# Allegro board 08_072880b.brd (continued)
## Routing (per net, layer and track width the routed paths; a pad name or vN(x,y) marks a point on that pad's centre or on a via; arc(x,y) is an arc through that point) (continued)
P5V0: length 3.1
  TOP w0.508: 41.02,55.31 J3.2 40.26,54.55 ; 44.32,54.55 J3.6 43.56,55.31
VCC: length 14.4
  TOP w0.127: 40.65,42.51 40.45,42.3 40.45,41.52 40.27,41.34 39.87,41.34 39.65,41.12 39.65,38.94 U1.E7
  TOP w0.203: 40.65,42.51 41.11,42.51 VCC.1 P3.2
3P3VAUX: length 3.2
  TOP w0.203: v1(65.31,17.72) C9.1 U4.8
  BOTTOM w0.508: 71.75,15.18 v1(72.39,15.81)
AINA+: length 23.6
  TOP w0.203: LKA.1 34.48,26.44 36.19,24.73 36.19,23.35 35.69,22.85 33.26,22.85 27.65,17.23 27.65,14.73 27.44,14.53 JP3.2 R70.2
AINA-: length 23.2
  TOP w0.203: JP2.1 JP4.2 28.41,14.53 28.21,14.73 28.21,17 33.49,22.29 35.92,22.29 36.75,23.11 36.75,24.9 36.76,24.91 37.36,25.51 38.29,26.44 LKA.7
AINB+: length 23.6
  TOP w0.203: R43.2 JP7.2 13.64,27.44 13.84,27.24 16.11,27.24 21.4,32.53 21.4,34.96 22.22,35.78 24.01,35.78 24.02,35.79 24.62,36.39 25.55,37.33 LKB.1
AINB-: length 23.3
  TOP w0.203: LKB.7 25.55,33.52 23.84,35.22 22.46,35.22 21.96,34.73 21.96,32.3 16.34,26.68 13.84,26.68 13.64,26.48 JP8.2 JP6.1
AINC+: length 23.2
  TOP w0.203: LKC.2 25.55,39.76 24.62,40.7 24.02,41.3 24.01,41.31 22.22,41.31 21.4,42.13 21.4,44.56 16.11,49.85 13.84,49.85 13.64,49.64 JP11.2 R59.2
AINC-: length 23.7
  TOP w0.203: JP10.3 JP12.2 13.64,50.61 13.84,50.41 16.34,50.41 21.96,44.79 21.96,42.36 22.46,41.87 23.84,41.87 25.55,43.57 LKC.8
AIND+: length 23.2
  TOP w0.203: LKD.2 34.48,50.65 36.19,52.36 36.19,53.74 35.69,54.24 33.26,54.24 27.65,59.86 27.65,62.36 27.44,62.56 JP15.2 JP13.1
AIND-: length 23.6
  TOP w0.203: JP14.3 JP16.2 28.41,62.56 28.21,62.36 28.21,60.09 33.49,54.8 35.92,54.8 36.75,53.98 36.75,52.19 36.76,52.18 37.36,51.58 38.29,50.65 LKD.8
BIA+: length 5.8
  TOP w0.203: JP1.1 v1(23.52,12.76)
  BOTTOM w0.203: R9.1 20.03,15 22.26,12.76 v1(23.52,12.76)
BIA-: length 6.3
  TOP w0.203: JP2.3 v1(32.01,12.76)
  BOTTOM w0.203: R11.1 35.37,16.13 v1(32.01,12.76)
BIB+: length 5.8
  TOP w0.203: JP5.1 v1(11.87,31.38)
  BOTTOM w0.203: R38.1 14.11,34.87 11.87,32.64 v1(11.87,31.38)
BIB-: length 6.3
  TOP w0.203: JP6.3 v1(11.87,22.9)
  BOTTOM w0.203: v1(11.87,22.9) 15.24,19.53 R39.1
BIC+: length 4.7
  TOP w0.203: v1(11.87,46.09) 12,46.09 12,46.09 JP9.3
  BOTTOM w0.203: v1(11.87,46.09) 11.87,45.39 13.67,43.6 R50.1
BIC-: length 4.1
  TOP w0.203: JP10.1 v1(11.87,54.57)
  BOTTOM w0.203: v1(11.87,54.57) 11.87,56.54 12.27,56.94 R55.1
BID+: length 4.7
  TOP w0.203: JP13.3 v1(23.9,64.33)
  BOTTOM w0.203: v1(23.9,64.33) 23.19,64.33 21.41,62.54 R66.1
BID-: length 4.1
  TOP w0.203: JP14.1 v1(32.39,64.33)
  BOTTOM w0.203: R67.1 34.75,63.93 34.35,64.33 v1(32.39,64.33)
BOA+: length 11.2
  TOP w0.203: JP3.1 v1(25.9,13.53)
  BOTTOM w0.203: v1(25.9,13.53) 23.59,13.53 21.09,16.02 C20.2 R36.2 C24.2 A1.1
BOA-: length 12
  TOP w0.203: JP4.1 v1(29.96,13.53)
  BOTTOM w0.203: A1.7 C25.2 R37.2 C21.2 34.43,16.19 31.76,13.53 v1(29.96,13.53)
BOB+: length 11.2
  TOP w0.203: JP7.1 v1(12.64,28.99)
  BOTTOM w0.203: v1(12.64,28.99) 12.64,31.31 15.14,33.81 C33.2 R48.2 C37.2 A2.1
BOB-: length 12
  TOP w0.203: JP8.1 v1(12.64,24.93)
  BOTTOM w0.203: v1(12.64,24.93) 12.64,23.14 15.3,20.47 C34.2 R49.2 C38.2 A2.7
BOC+: length 19.3
  TOP w0.203: JP11.1 v1(12.64,48.09)
  BOTTOM w0.203: A3.1 C47.2 R64.2 C43.2 19.54,43.03 18.44,41.92 13.86,41.92 11.29,44.49 11.29,46.75 v1(12.64,48.09)
BOC-: length 19.1
  TOP w0.203: JP12.1 v1(12.64,52.16)
  BOTTOM w0.203: A3.7 C48.2 R65.2 C44.2 18.27,57.63 17.29,58.61 12.46,58.61 11.32,57.47 11.32,53.42 12.18,52.55 12.24,52.55 v1(12.64,52.16)
BOD+: length 19.3
  TOP w0.203: JP15.1 v1(25.9,63.56)
  BOTTOM w0.203: v1(25.9,63.56) 24.57,64.88 22.26,64.88 19.74,62.36 19.74,57.76 20.84,56.66 C53.2 R79.2 C57.2 A4.1
BOD-: length 19.1
  TOP w0.203: JP16.1 v1(29.96,63.56)
  BOTTOM w0.203: v1(29.96,63.56) 30.35,63.96 30.35,64.02 31.22,64.88 35.27,64.88 36.44,63.72 36.44,58.92 35.45,57.93 C54.2 R80.2 C58.2 A4.7
CSN: length 6.1
  TOP w0.203: R16.1 42.95,34.81 42.55,35.21 v1(42.55,36.14) 41.97,36.14 41.97,36.14 U1.H9
  BOTTOM w0.203: v1(42.55,36.14) 42.55,35.33 43.07,34.81 R16.1
ENABLE: length 22.6
  BOTTOM w0.127: 40.55,37.34 35.8,37.34 35.65,37.49 35.65,38.15 v2(35.26,38.54)
  BOTTOM w0.203: 40.55,37.34 41.29,36.6 41.29,34.91 45.55,30.65 51.78,30.65 52.13,30.29 ENABLE.2
GA0: length 7.1
  TOP w0.203: v1(73.66,13.27) 72.9,14.03 69.44,14.03 68.83,13.42 U4.2
  BOTTOM w0.203: P1.C34 v1(73.66,13.27)
GA1: length 14.1
  TOP w0.203: U4.1 67.56,13.42 68.65,14.51 73.31,14.51 74.23,13.59 74.23,12.57 72.39,10.73 v1(71.12,10.73)
  BOTTOM w0.203: 71.75,11.37 v1(71.12,10.73)
IN_LDO: length 20.4
  TOP w0.203: v2(37.66,39.34) U1.C5 U1.C6
  BOTTOM w0.127: 40.45,42.02 40.45,40.58 39.62,39.75 38.06,39.75 v2(37.66,39.34)
  BOTTOM w0.203: 40.45,42.02 42.8,44.37 42.8,47.75 IN_LDO.1 45.4,51.44 J3.5
INA+: length 12.8
  TOP w0.203: A+.1 INA+.1 R70.1 R1.2
INA-: length 12.8
  TOP w0.203: A-.1 INA-.1 JP2.2 R2.2
INB+: length 12.8
  TOP w0.203: R3.2 R43.1 INB+.1 B+.1
INB-: length 12.8
  TOP w0.203: R4.2 JP6.2 INB-.1 B-.1
INC+: length 12.8
  TOP w0.203: C+.1 INC+.1 R59.1 R5.2
INC-: length 12.6
  TOP w0.203: R6.2 JP10.2 INC-.1 C-.1
IND+: length 12.8
  TOP w0.203: D+.1 IND+.1 JP13.2 R7.2
IND-: length 12.7
  TOP w0.203: R8.2 JP14.2 IND-.1 D-.1
OUT_LDO: length 12.4
  TOP w0.203: OUT_LDO.1 53.52,49.34 J2.1 51.31,49.34 50.04,48.07 P3.1 ; U1.D6 v2(39.26,39.34)
  L3_PWR w0.508: P3.1 47.5,48.07 ; P3.1 48.51,48.83 ; P3.1 49.53,48.07
OUTA+: length 13.5
  BOTTOM w0.127: v2(39.26,36.14) 39.04,36.14 38.64,36.54 38.2,36.54 38.06,36.41 38.06,35.69
  BOTTOM w0.203: C2.2 37.44,33.65 37.95,34.15 37.95,34.16 38.06,34.27 38.06,35.69 ; v2(39.26,36.14) 39.26,33.77 40.83,32.19 v1(40.83,27.72)
OUTA-: length 13.3
  BOTTOM w0.203: 39.13,32.62 39.56,32.19 v1(39.56,27.53) ; 39.13,32.62 38.7,32.19 36.65,32.19 36.45,32.4 C1.2 ; 39.13,32.62 38.46,33.3 v2(38.46,36.14)
OUTB+: length 14.9
  BOTTOM w0.127: 34.74,36.54 35.88,36.54 36.06,36.36 v2(36.06,36.14)
  BOTTOM w0.203: 34.74,36.54 34.71,36.58 33.29,36.58 32.76,37.11 C4.2
  BOTTOM w0.254: v1(27.6,30.98) 31.67,30.98 36.06,35.36 v2(36.06,36.14)
OUTB-: length 16.8
  BOTTOM w0.203: C3.2 32.13,38.1 31.78,37.75 31.78,36.1 33.91,33.97
  BOTTOM w0.254: v2(35.26,36.14) 35.26,35.32 32.13,32.19 v1(26.34,32.19)
OUTC+: length 15.9
  BOTTOM w0.127: 34.1,41.35 34.61,41.35 34.86,41.1 34.86,40.7 35.03,40.54 35.65,40.54 v2(36.06,40.94)
  BOTTOM w0.203: v2(36.06,40.94) 36.06,41.73 31.69,46.1 v1(27.6,46.1) ; 34.1,41.35 33.28,41.35 32.79,40.86 C6.2
OUTC-: length 16.4
  BOTTOM w0.203: v1(26.34,44.83) 32.19,44.83 33.88,43.15 ; 33.88,43.15 35.26,41.77 v2(35.26,40.94) ; 33.88,43.15 31.94,41.21 31.94,39.54 32.2,39.28 C5.2
OUTD+: length 13.6
  BOTTOM w0.127: 38.06,41.35 38.06,40.68 38.23,40.51 38.82,40.51 v2(39.26,40.94)
  BOTTOM w0.152: C8.2 37.38,43.44 38.06,42.76
  BOTTOM w0.203: 38.06,42.76 38.06,41.35 ; v2(39.26,40.94) 39.26,42.94 40.83,44.51 v1(40.83,49.4)
OUTD-: length 13.6
  BOTTOM w0.203: v2(38.46,40.94) 38.46,43.41 39.56,44.51 39.56,45.02 ; 39.56,45.02 v1(39.56,49.59) ; 39.56,45.02 36.85,45.02 36.45,44.63 C7.2
PMODE: length 21.4
  BOTTOM w0.127: v2(36.06,38.54) 36.45,38.15 40.66,38.15
  BOTTOM w0.203: MODE.2 52.13,31.43 51.78,31.08 45.76,31.08 41.68,35.15 41.68,37.13 40.66,38.15
R1A+: length 11.9
  TOP w0.203: U1.J6 38.23,35.12 38.23,34.23 38.46,34 38.46,33.67 39.56,32.56 LKA.10 39.56,30.16 39.18,29.78 36.13,29.78 35.75,29.4 LKA.3
R1A-: length 11.7
  TOP w0.203: U1.J7 39.26,34.14 40.83,32.56 LKA.12 40.83,29.86 40.25,29.27 37.53,29.27 37.02,28.77 LKA.5
R1B+: length 14.4
  TOP w0.254: U1.J2 34.79,34.87 32.7,34.87 32.45,34.62 32.45,32.54 32.16,32.25 LKB.10 29.62,32.25 28.89,32.97 28.89,35.8 28.64,36.06 LKB.3
R1B-: length 14.6
  TOP w0.254: U1.J3 31.69,30.98 LKB.12 28.92,30.98 28.38,31.51 28.38,34.53 28.13,34.79 LKB.5
R1C+: length 14.4
  TOP w0.203: LKC.4 28.59,41.03 28.79,41.24 28.79,44.02 29.62,44.84 LKC.9
  TOP w0.254: U1.A2 34.79,42.21 32.7,42.21 32.45,42.47 32.45,44.55 32.16,44.84 LKC.9
R1C-: length 14.4
  TOP w0.203: LKC.6 27.61,42.3 28.38,43.08 28.38,45.73 28.77,46.11 LKC.11 31.69,46.11 U1.A3
R1D+: length 11.7
  TOP w0.203: U1.A6 38.23,41.97 38.23,42.86 38.46,43.09 38.46,43.42 39.56,44.53 LKD.9 39.56,46.58 38.84,47.31 36.13,47.31 35.75,47.69 LKD.4
R1D-: length 11.8
  TOP w0.203: U1.A7 39.26,42.95 40.83,44.53 LKD.11 40.83,47.18 40.2,47.82 37.27,47.82 37.02,48.07 LKD.6
R2A+: length 5.5
  TOP w0.203: U1.J4 35.75,34.24 LKA.4 LKA.2
R2A-: length 5.5
  TOP w0.203: U1.J5 36.83,34.52 36.83,33.43 37.02,33.24 LKA.6 LKA.8
R2B+: length 6
  TOP w0.254: U1.F1 33.11,37.74 32.58,37.21 32.58,36.91 31.67,36 30.7,36 LKB.4 LKB.2
R2B-: length 6
  TOP w0.254: LKB.8 LKB.6 30.7,34.73 31.67,34.73 33.88,36.94 U1.G1
R2C+: length 6
  TOP w0.203: LKC.1 LKC.3
  TOP w0.254: U1.D1 33.11,39.34 32.58,39.88 32.58,40.18 31.67,41.08 30.7,41.08 LKC.3
R2C-: length 6
  TOP w0.203: U1.C1 33.83,40.14 31.67,42.3 LKC.5 LKC.7
R2D+: length 5.5
  TOP w0.203: U1.A4 35.75,42.85 LKD.3 LKD.1
R2D-: length 5.5
  TOP w0.203: U1.A5 36.83,42.57 36.83,43.66 37.02,43.85 LKD.5 LKD.7
REFSNS: length 4.8
  TOP w0.203: REFS.1 45.4,33.33 45.19,33.54 R81.2
SCL: length 5.9
  TOP w0.203: U4.6 70.1,18.5 70.71,19.11 73.03,19.11 v1(73.72,18.41)
  BOTTOM w0.203: P1.C30 v1(73.72,18.41)
SCLK: length 5.3
  TOP w0.203: R23.1 R15.1 43.43,39.34 v1(42.55,39.34) U1.D9
  BOTTOM w0.203: R15.1 43.43,39.34 v1(42.55,39.34)
SCLK_R: length 26.4
  TOP w0.203: R23.2 48.66,40.14 52.9,44.39 58.55,44.39 v1(62.36,48.2)
  BOTTOM w0.203: v1(62.36,48.2) 64.14,48.2 66.67,50.74
SDA: length 3.6
  TOP w0.203: U4.5 73.15,17.72 v1(73.72,17.14)
  BOTTOM w0.203: P1.C31 v1(73.72,17.14)
SDI: length 4.4
  TOP w0.203: R19.1 43.62,38.01 43.09,38.54 v1(42.55,38.54) U1.E9
  BOTTOM w0.203: R19.1 43.62,38.01 43.09,38.54 42.66,38.54 42.65,38.54 42.55,38.54 v1(42.55,38.54)
SDOA: length 4.9
  TOP w0.203: R13.1 43.62,35.88 v1(42.55,36.94) 41.97,36.94 41.97,36.94 U1.G9
  BOTTOM w0.203: v1(42.55,36.94) 43.62,35.88 R13.1
SDOB: length 4.6
  TOP w0.203: R14.1 43.65,36.94 42.85,37.74 v1(42.55,37.74) U1.F9
  BOTTOM w0.203: v1(42.55,37.74) 42.82,37.74 43.62,36.94 R14.1
SDOC: length 4.4
  TOP w0.203: R20.1 43.62,41.21 v1(42.55,40.14) 41.97,40.14 41.97,40.14 U1.C9
  BOTTOM w0.203: R29.2 v1(42.55,40.14)
SDOD: length 5.1
  TOP w0.203: R17.1 43.07,42.28 42.55,41.76 v1(42.55,40.94) 41.97,40.94 41.97,40.94 U1.B9
  BOTTOM w0.203: R68.2 43.43,40.94 v1(42.55,40.94)
SJA+: length 1.7
  BOTTOM w0.203: v2(36.86,36.14) 36.86,35.13 36.45,34.73 C1.1
SJA-: length 1.6
  BOTTOM w0.203: C2.1 37.4,35.22 37.66,35.47 v2(37.66,36.14)
SJB+: length 1.6
  BOTTOM w0.152: C3.1 34.1,38.1 34.46,37.74 v2(35.26,37.74)
SJB-: length 1.6
  BOTTOM w0.152: C4.1 34.38,37.15 34.58,36.94 v2(35.26,36.94)
SJC+: length 1.5
  BOTTOM w0.203: v2(35.26,39.34) 34.43,39.34 34.36,39.28 C5.1
SJC-: length 1.5
  BOTTOM w0.203: C6.1 34.36,40.23 34.45,40.14 v2(35.26,40.14)
SJD+: length 1.7
  BOTTOM w0.203: C7.1 36.45,41.35 v2(36.86,40.94)
SJD-: length 1.6
  BOTTOM w0.203: v2(37.66,40.94) 37.34,41.26 C8.1
UNNAMED_2_ADAQ43804_I54_DNC4: length 7.4
  TOP w0.127: 39.92,34.89 39.66,35.15 39.66,36.43 39.53,36.56 38.84,36.56 U1.G6
  TOP w0.203: 39.92,34.89 41.27,33.54 R81.1
UNNAMED_3_CN12PV3_I71_P1: length 41.8
  BOTTOM w0.203: R24.2 45.32,34.81 45.85,35.34 50.63,35.34 60.54,45.25 60.54,52.39 69.35,61.2 71.04,61.2 P2.1
UNNAMED_3_CN12PV3_I71_P2: length 41.9
  TOP w0.203: v1(69.41,63.56) 69.85,64.01 P2.2
  BOTTOM w0.203: R25.2 51.54,38.01 59.32,45.79 59.32,53.48 v1(69.41,63.56)
UNNAMED_3_CN12PV3_I71_P3: length 54.5
  TOP w0.203: P2.3 72.72,65.14 74.32,65.14 74.98,64.48 74.98,61 74.32,60.34 70.36,60.34 69.41,61.29 v1(69.41,61.85)
  BOTTOM w0.203: R26.2 50.58,35.88 60.13,45.43 60.13,52.58 v1(69.41,61.85)
UNNAMED_3_CN12PV3_I71_P4: length 46.6
  TOP w0.203: v1(69.41,64.45) 68.8,65.06 68.8,67.85 70.04,69.09 P2.4
  BOTTOM w0.203: v1(69.41,64.45) 58.92,53.96 58.92,45.97 52.03,39.08 R27.2
UNNAMED_3_CN12PV3_I71_P7: length 44.6
  TOP w0.203: P2.7 72.64,62.67 v1(69.41,62.67)
  BOTTOM w0.203: R28.1 51.06,36.94 59.73,45.61 59.73,53 v1(69.41,62.67)
UNNAMED_3_CN12PV3_I71_P8: length 44.9
  TOP w0.203: v1(69.41,65.24) 69.96,65.24 69.97,65.25 72.04,65.25 73.28,64.01 P2.8
  BOTTOM w0.203: v1(69.41,65.24) 58.51,54.35 58.51,46.14 52.51,40.14 R29.1
UNNAMED_3_CN12PV3_I71_P9: length 46.5
  TOP w0.203: v1(69.41,66.1) 69.41,67.56 69.66,67.82 72.58,67.82 P2.9
  BOTTOM w0.203: R68.1 52.99,41.21 58.1,46.32 58.1,54.8 v1(69.41,66.1)
UNNAMED_3_CN160PCDGH_I25_N8: length 35.4
  TOP w0.203: R13.2 46.69,35.88 53.44,42.63 60.81,42.63 v1(62.36,41.08)
  BOTTOM w0.203: v1(62.36,41.08) 64.58,41.08 65.71,39.95 68.2,39.95 68.57,40.32 68.57,40.81 71.5,43.74 71.99,43.74 72.39,44.14 72.39,45.02 71.75,45.66
UNNAMED_3_CN160PCDGH_I25_N9: length 31.7
  TOP w0.203: R14.2 47.18,36.94 53.34,43.1 61.54,43.1 v1(62.36,42.29)
  BOTTOM w0.203: 71.75,44.39 71.56,44.39 68.4,41.22 66.42,41.22 65.35,42.29 v1(62.36,42.29)
UNNAMED_3_CN160PCDGH_I25_N30: length 1.3
  BOTTOM w0.203: 71.75,17.72 71.75,16.45
UNNAMED_3_CN160PCDGH_I35_N6: length 27
  TOP w0.203: R15.2 48.17,39.08 53.07,43.98 59.22,43.98 v1(62.36,47.12)
  BOTTOM w0.203: P1.G6 67.32,47.57 66.24,47.57 65.79,47.12 v1(62.36,47.12)
UNNAMED_3_CN160PCDGH_I35_N7: length 45.9
  TOP w0.203: R16.2 46.22,34.81 53.62,42.21 60.15,42.21 v1(62.34,40.02)
  BOTTOM w0.203: P1.G7 68.57,46.3 73.27,46.3 74.22,45.35 74.22,41.64 73.79,41.21 70.8,41.21 68.28,38.68 66.34,38.68 65.01,40.02 v1(62.34,40.02)
UNNAMED_3_CN160PCDGH_I35_N9: length 33.2
  TOP w0.203: R17.2 49.64,42.28 52.57,45.2 57.2,45.2 v1(62.36,50.36)
  BOTTOM w0.203: 67.95,44.39 67.32,45.01 62.02,45.01 61.37,45.66 61.37,49.37 v1(62.36,50.36)
UNNAMED_3_CN160PCDGH_I38_N7: length 25.7
  TOP w0.203: v1(62.36,46.04) 59.87,43.55 53.21,43.55 47.68,38.01 R19.2
  BOTTOM w0.203: 66.67,46.93 65.79,46.04 v1(62.36,46.04)
UNNAMED_3_CN160PCDGH_I38_N8: length 29.9
  TOP w0.203: R20.2 49.15,41.21 52.73,44.79 57.87,44.79 v1(62.36,49.28)
  BOTTOM w0.203: 66.67,45.66 66.43,45.42 62.19,45.42 61.79,45.82 61.79,48.7 v1(62.36,49.28)
UNNAMED_4_ADP7142_I61_SS: length 2.1
  TOP w0.203: U3.5 51.05,57.91 51.78,57.18 C14.2
UNNAMED_4_CN3P_I47_N3: length 24
  TOP w0.203: v1(61.72,64.07) R10.2
  BOTTOM w0.203: v1(61.72,64.07) 61.72,59.88 58.6,56.76 54.98,56.76 53.61,55.39 53.61,47.91 52.5,46.8 J2.3
UNNAMED_6_ADA46252V2_I193_: length 4.2
  BOTTOM w0.203: A1.5 31.6,20.43 32.13,20.96 C19.1 R22.2
UNNAMED_6_ADA46252V2_I193__1: length 4.1
  BOTTOM w0.203: R35.2 R37.1 C25.1 32.03,19.16 A1.6
UNNAMED_6_ADA46252V2_I194_: length 4.1
  BOTTOM w0.203: R30.2 R36.1 C24.1 23.5,17.89 A1.2
UNNAMED_6_ADA46252V2_I194__1: length 4.2
  BOTTOM w0.203: R21.2 C18.1 23.4,19.69 23.93,19.16 A1.3
UNNAMED_6_ADA46252V2_I198_: length 4.2
  BOTTOM w0.203: A2.5 19.54,23.3 20.07,22.78 C32.1 R45.2
UNNAMED_6_ADA46252V2_I198__1: length 4.1
  BOTTOM w0.203: A2.6 18.27,22.88 C38.1 R49.1 R47.2
UNNAMED_6_ADA46252V2_I199_: length 4.2
  BOTTOM w0.203: A2.3 18.27,30.98 18.8,31.5 C31.1 R44.2
UNNAMED_6_ADA46252V2_I199__1: length 4.1
  BOTTOM w0.203: R46.2 R48.1 C37.1 17,31.4 A2.2
UNNAMED_6_ADA46252V2_I202_: length 4.2
  BOTTOM w0.203: R60.2 C41.1 16.47,45.85 17,46.37 A3.3
UNNAMED_6_ADA46252V2_I202__1: length 4.1
  BOTTOM w0.203: A3.2 18.27,46.07 C47.1 R64.1 R62.2
UNNAMED_6_ADA46252V2_I203_: length 4.2
  BOTTOM w0.203: A3.5 15.73,54.17 15.2,54.7 C42.1 R61.2
UNNAMED_6_ADA46252V2_I203__1: length 4.1
  BOTTOM w0.203: R63.2 R65.1 C48.1 17,54.59 A3.6
UNNAMED_6_ADA46252V2_I205_: length 4.2
  BOTTOM w0.203: R75.2 C51.1 23.66,59.73 24.19,59.2 A4.3
UNNAMED_6_ADA46252V2_I205__1: length 4.1
  BOTTOM w0.203: A4.2 23.88,57.93 C57.1 R79.1 R77.2
UNNAMED_6_ADA46252V2_I206_: length 4.1
  BOTTOM w0.203: A4.6 32.41,59.2 C58.1 R80.1 R78.2
UNNAMED_6_ADA46252V2_I206__1: length 4.2
  BOTTOM w0.203: A4.5 31.98,60.47 32.51,61 C52.1 R76.2
UNNAMED_6_CAP_I59_N1: length 2.1
  BOTTOM w0.203: C20.1 R21.1 R12.2
UNNAMED_6_CAP_I62_N1: length 2.1
  BOTTOM w0.203: R12.1 R9.2 C16.1
UNNAMED_6_CAP_I66_N1: length 2.1
  BOTTOM w0.203: C17.1 R11.2 R18.1
UNNAMED_6_CAP_I72_N1: length 2
  BOTTOM w0.203: C21.1 R22.1 R18.2
UNNAMED_6_CAP_I84_N1: length 2.1
  BOTTOM w0.203: R41.2 R44.1 C33.1
UNNAMED_6_CAP_I92_N1: length 2.1
  BOTTOM w0.203: R41.1 R38.2 C29.1
UNNAMED_6_CAP_I94_N1: length 2
  BOTTOM w0.203: R42.2 R45.1 C34.1
UNNAMED_6_CAP_I103_N1: length 2.1
  BOTTOM w0.203: R42.1 R39.2 C30.1
UNNAMED_6_CAP_I124_N1: length 2.1
  BOTTOM w0.203: R57.2 R60.1 C43.1
UNNAMED_6_CAP_I132_N1: length 2.1
  BOTTOM w0.203: R57.1 C39.1 R50.2
UNNAMED_6_CAP_I134_N1: length 2
  BOTTOM w0.203: R58.2 R61.1 C44.1
UNNAMED_6_CAP_I140_N1: length 2.1
  BOTTOM w0.203: R55.2 C40.1 R58.1
UNNAMED_6_CAP_I162_N1: length 2.1
  BOTTOM w0.203: C53.1 R75.1 R72.2
UNNAMED_6_CAP_I169_N1: length 2
  BOTTOM w0.203: C54.1 R76.1 R73.2
UNNAMED_6_CAP_I182_N1: length 2.1
  BOTTOM w0.203: R72.1 C49.1 R66.2
UNNAMED_6_CAP_I187_N1: length 2.1
  BOTTOM w0.203: R67.2 C50.1 R73.1
VLOGIC: length 19.4
  TOP w0.127: U1.C8 40.46,40.55 40.46,41.05 40.73,41.31 41.14,41.31 41.34,41.52
  TOP w0.203: VLOGIC.1 J2.2 52.25,48.07 48.03,43.85 43.68,43.85 41.34,41.52
VNEG: length 9.6
  BOTTOM w0.508: A4.4 C56.1 25.98,61.99 v1(26.37,61.61) ; A3.4 C46.1 14.21,48.17 v1(14.59,48.55) ; A2.4 C36.1 v1(21.02,29.02) ; v1(25.87,21.9) C23.1 A1.4
  vias: v1(52.77,3.16) v1(52.77,2.4) v1(52.77,1.64)
VPOS: length 9.8
  BOTTOM w0.508: A2.8 C35.1 v1(14.97,22.61) ; A1.8 C22.1 v1(32.3,15.86) ; A4.8 C55.1 v1(29.96,55.18) ; A3.8 C45.1 v1(21.02,52.21)
  vias: v1(41.56,3.16) v1(41.56,2.4) v1(41.56,1.64)
VS+: length 6.6
  L3_PWR w0.508: ENABLE.1 54.17,29.35 ; ENABLE.1 53.4,28.46 ; ENABLE.1 53.4,30.24 ; MODE.1 54.17,32.37 ; MODE.1 53.4,33.26 ; MODE.1 53.4,31.48 ; 41.02,52.51 J3.1 40.26,53.28
  vias: v2(36.06,40.14) v2(36.06,39.34) v2(36.86,40.14) v2(36.86,39.34) v2(39.26,37.74)
VS-: length 0.8
  L3_PWR w0.508: J3.3 42.29,52.51
  vias: v2(36.06,37.74) v2(36.06,36.94) v2(36.86,37.74) v2(36.86,36.94)

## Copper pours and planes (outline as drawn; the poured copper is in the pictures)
3V3IN on TOP: 44.2,67.22 44.2,65.72 42.99,65.72 42.99,67.22
3V3IN on BOTTOM: 42.99,67.22 42.99,63.31 58.23,63.31 58.23,67.22
+3V3_FMC on L3_PWR: 58.23,75.56 58.23,0.63 77.66,0.63 77.66,75.56 ; 1 cut-out
+3V3_PMOD on BOTTOM: 77.66,75.56 77.66,72.64 70.1,72.64 62.67,65.21 58.62,65.21 58.61,65.23 58.61,67.6 40.69,67.6 40.69,75.56
AGND on TOP: 0.64,75.56 77.66,75.56 77.66,0.63 0.64,0.63 ; 35 cut-outs
AGND on BOTTOM: 0.64,75.56 77.66,75.56 77.66,0.63 0.64,0.63 ; 27 cut-outs
AGND on L2_GND: 0.64,75.56 77.66,75.56 77.66,0.63 0.64,0.63 ; 3 cut-outs
P5V0 on TOP: 44.77,53.66 44.77,55.05 43.69,56.13 43.69,59.18 38.77,59.18 38.77,55.29 40.4,53.66
3P3VAUX on L3_PWR: 64.45,18.92 64.45,14.99 72.83,14.99 72.83,18.92
OUT_LDO on L3_PWR: 39.05,40.22 39.05,39.13 42.63,39.13 42.63,46.16 49.77,46.16 49.77,49.11 41.34,49.11 41.34,40.22
UNNAMED_4_ADP7142_I61_EN on TOP: 49.63,59.18 49.63,53.37 53.37,53.37 53.37,59.18
UNNAMED_4_ADP7142_I61_SENSE on TOP: 44.01,59.18 44.01,57.64 48.23,57.64 48.23,59.18
UNNAMED_4_CAP_I16_N1 on TOP: 48.51,65.56 46.01,65.56 46.01,68.2 43.45,68.2 43.45,74.33 48.51,74.33
UNNAMED_4_CAP_I18_N2 on TOP: 50.74,65.41 50.74,65.09 53.47,65.09 53.47,65.85 52.01,65.85 52.01,65.41
UNNAMED_4_CAP_I37_N2 on TOP: 43.12,64.04 43.12,61.25 44.64,61.25 44.64,64.04
UNNAMED_4_CAP_I41_N1 on TOP: 48.51,65.34 48.51,65.06 47.18,65.06 47.18,64.1 45.02,64.1 45.02,65.34
UNNAMED_4_CAP_I45_N1 on TOP: 50.74,64.36 50.74,60.96 52.58,60.96 52.58,59.4 53.91,59.4 53.91,63.31 51.78,63.31 51.78,64.36
UNNAMED_4_CAP_I45_N2 on TOP: 56.62,69.58 56.62,57.94 53.69,57.94 53.69,59.18 54.29,59.18 54.29,63.31 55.75,63.31 55.75,66.08 52.22,66.08 52.22,69.58
UNNAMED_4_DIOLED_I6_P on TOP: 40.69,71.87 40.69,70.55 43.24,70.55 43.24,71.87
UNNAMED_4_DIOSCHOTTKY_I56_P on TOP: 50.74,66.96 50.74,66.07 52.02,66.07 52.02,74.33 48.77,74.33 48.77,67.09 48.9,66.96
UNNAMED_4_FERRITE_I62_N2 on TOP: 44.45,67.82 44.45,65.54 45.72,65.54 45.72,67.82
UNNAMED_4_ICLT8362_I19_RT on TOP: 52.01,63.53 53.88,63.53 53.88,64.93 50.74,64.93 50.74,64.55 52.01,64.55
UNNAMED_4_ICLT8362_I19_VC on TOP: 48.51,64.36 48.51,62.58 45.05,62.58 45.05,63.85 47.5,63.85 47.5,64.36
VNEG on BOTTOM: 54.04,3.72 54.04,0.63 47.69,0.63 47.69,4.33 48.86,5.5 50.58,5.5 51.93,4.15 53.61,4.15
VNEG on L3_PWR: 20,66.42 28.77,66.42 28.77,23.53 57.59,23.53 57.59,0.63 47.49,0.63 47.49,18.16 28.61,18.16 28.61,6.86 8.95,6.86 8.95,20.03 17.34,20.03 17.34,26.33 11.87,26.33 11.87,50.67 21.91,50.67 21.91,54.99 20,54.99
VPOS on BOTTOM: 40.32,3.72 40.32,0.63 46.67,0.63 46.67,4.33 45.5,5.5 43.78,5.5 42.43,4.15 40.75,4.15
VPOS on L3_PWR: 0.64,75.56 38.23,75.56 38.23,57.02 36,57.02 36,52.51 29.4,52.51 29.4,67.06 19.37,67.06 19.37,54.36 21.27,54.36 21.27,51.31 11.24,51.31 11.24,25.69 16.7,25.69 16.7,20.66 8.32,20.66 8.32,6.22 29.25,6.22 29.25,17.53 46.85,17.53 46.85,0.63 0.64,0.63
VS+ on L3_PWR: 36.64,56.39 48.83,56.39 48.83,54.17 41.34,54.17 41.34,49.75 40.7,49.75 40.7,40.86 38.42,40.86 38.42,38.49 40.96,38.49 40.96,36.45 37.66,36.45 37.66,38.54 32.45,38.54 32.45,30.48 45.15,30.48 45.15,34.54 57.59,34.54 57.59,24.17 29.4,24.17 29.4,51.88 36.64,51.88 ; 3 cut-outs
VS- on L3_PWR: 38.86,75.56 57.59,75.56 57.59,35.18 44.51,35.18 44.51,31.11 33.08,31.11 33.08,37.91 37.02,37.91 37.02,35.81 41.59,35.81 41.59,38.49 43.27,38.49 43.27,45.53 50.41,45.53 50.41,49.75 41.97,49.75 41.97,53.53 49.47,53.53 49.47,57.02 38.86,57.02

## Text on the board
User.Comments: SEE NOTE #5 (4 PLACES) | SEE DETAIL A (2 PLACES) | WITH LEAD-FREE AND RoHS PCB ASSEMBLY STANDARDS (EU RoHS | DIRECTIVE 2002/95/EC). | 5.    INSTALL STANDOFF (M000160) ON SECONDARY SIDE. | TOGETHER WITH THE BOARD. | SIDE OF THE BOARD. | 4.    RoHS COMPLIANCE: ASSEMBLY VENDOR SHOULD ASSURE COMPLIANCE | 6.    INSTALL SHUNT CONNECTOR (M026786) TO THE FOLLOWING JUMPER: | REMAINING UNINSTALLED SHUNT CONNECTORS SHOULD BE SHIPPED | 7.    BOARDS TO BE SHIPPED SINGULATED AFTER ASSEMBLY PROCESS. | 8.    SMOOTHEN EDGES AND FREE FROM BURRS AFTER DEPANELIZATION PROCESS. | 3.    REPAIRS ARE NOT ALLOWED IN SOLDERMASK FREE AREAS ON EITHER | 2.    REPAIRS PER IPC-7711/21(LATEST REVISION) ARE ALLOWED. | LKA | LKB | LKC | LKD | PIN 9 AND PIN 10 | PIN 11 AND PIN 12 | PIN 1 AND PIN 2 | PIN 7 AND PIN 8 | J3 | J1 | J2 | PIN 5 AND PIN 6 | PIN 3 AND PIN 4
Ref Des/Assembly Top: 3 | 1 | 2 | 12 | 11 | A | C
Ref Des/Silkscreen Top: 11 | 12 | C | A | DIS | LP | EV-ADAQ43XX-4FMCZ | 1
PAGE_OUTLINE: FAB NOTES REVISION: 2ND NOVEMBER 2022 | 8.   IMPEDANCE REQUIREMENTS: IF NO STACKUP IS DEFINED, THE VENDOR IS ALLOWED TO ADJUST THE DIELECTRIC | 13.  PLATING SPECIFICATION: | 9.   FILLET OPTIONS TO ENHANCE RELIABILITY AT PAD JUNCTIONS WHERE SPACING PERMITS. | 10.  THIEVING: | 11.  LAYER TO LAYER REGISTRATION SHALL BE WITHIN 0.003 INCHES. | 12.  DRILL SIZES ARE FINISHED HOLE SIZES. ALL HOLES SHALL BE LOCATED WITHIN 0.005 INCHES DTP, | 14.  SURFACE FINISH: | 15.  SOLDERMASK: | 1.   DIMENSIONS ARE IN INCHES (EXCEPT WHERE NOTED). | ALL DOCUMENTS & SPECIFICATIONS REFERRED TO BELOW SHOULD BE THE LATEST REVISIONS. | 2.  BOARD MATERIAL:(USE CHECKED ITEMS) | 3.   ALL LAMINATES & BONDING MATERIALS SHOULD BE SELECTED FROM IPC-4101 OR IPC-4103,(TG>170 DEGC TD>300 DEGC) | 4.   REFER TO IPC-6010 SERIES, CLASS 2 FOR FABRICATION. | 5.   REFER TO LAMINATION DIAGRAM FOR OVERALL BOARD THICKNESS, TOLERANCE APPLIES AFTER ALL LAMINATION AND PLATING | 6.   BOW & TWIST NOT TO EXCEED 0.0075 INCHES (0.75%) PER LINEAR INCH AND SHOULD BE MEASURED PER IPC-TM-650, METHOD 2.4.22. | 7.   ACCEPTABILITY PER ADI SPECIFICATION TST00115. | 16.  APPLY SILKSCREEN TO BOTH SIDES USING A NON-CONDUCTIVE, EPOXY BASED INK PER ARTWORK. | ROHS COMPLIANCE NOTE: | HOMOGENOUS MATERIALS IN THIS BOARD SHALL BE COMPLAINT WITH THE EU DIRECTIVE 2002/95/EC | ( ) FILLETS ALLOWED | (X) FILLETS NOT ALLOWED | (X) VENDOR MAY ADD THIEVING TO COMPENSATE FOR LOW COPPER DENSITY AREAS MAINTAINING A MINIMUM | ( ) VENDOR MAY NOT ADD THIEVING TO COMPENSATE FOR LOW COPPER DENSITY AREAS. | (X) LPI | ( ) OTHER_________ | COLOR | (X) GREEN | (X) WHITE | ( ) OTHER | HINDER PROPER SOLDER WICKING. BARREL RELIEF ON SOLDERMASK ALLOWED IN UNFILLED VIA IN PAD HOLES. | (X) REFER TO LAMINATION DIAGRAM FOR FINISHED COPPER WEIGHT/THICKNESS REQUIRMENTS | (X) IMMERSION GOLD (ENIG) 1.58-3.94 MICRO INCHES OVER 118-236 MICRO INCHES MIN. OF ELECTROLESS NICKEL PER IPC-4552 | ( ) OSP (ORGANIC SOLDERABILITY PRESERVATIVE) | ( ) IMMERSION SILVER | ( ) SOFT WIRE BONDABLE GOLD 30-50 MICRO INCHES OF SOFT WIRE | ( ) EDGE CONNECTOR FINGERS ARE TO BE PLATED WITH 100 MICRO-INCHES(.0001") OF LOW STRESS | THICKNESS & TRACE WIDTHS TO MEET THE IMPEDANCE REQUIREMENT. IF SPECIFIED, THE VENDOR MUST | TRACE WIDTH & SPACING THAT IMPACT THE REQUIREMENTS MUST HAVE WRITTEN APPROVAL FROM ADI. | MINIMUM BARREL PLATING OF 0.001 INCHES. PLATED HOLES SHALL NOT BE ROUGH OR IRREGULAR SO AS TO | SOLDERMASK OVER BARE COPPER OR BARE GOLD (BOTH SIDES) TO MEET IPC-SM-840. | IF PRESENT,DO NOT MODIFY SOLDERMASK DEFINED PADS (MASK OPENINGS LESS THAN COPPER PAD) WITHOUT APPROVAL. | MEET THE REQUIREMENTS LISTED IN THE IMPEDANCE TABLE. ANY ADJUSTMENT MADE TO THE DEFINED STACKUP, | PROCESSES. FINISHED THICKNESS MEASURED FROM TOP COPPER TO BOTTOM COPPER. | (X) ISOLA 370HR OR S1000-2 OR IT180 OR EQUIVALENT | ( ) ISOLA FR408HR OR EQUIVALENT | ( ) ISOLA IS410 | ( ) MEGTRON 6 | ( ) NELCO 4000-13 | ( ) ROGERS 4350B | ( ) ROGERS 3003 | ( ) ARLON 85N | ( ) EM370D | ( ) OTHER ________________________ | UL FLAMMABILITY RATING 94V-0. BOARD MATERIAL & CONSTRUCTION SHALL MEET THE REQUIREMENTS OF UL796/UL796F. | BONDABLE GOLD OVER 100-150 MICRO INCHES OF NICKEL | NICKEL UNDER 30 MICRO-INCHES (.0003') OF GOLD | 0.100 INCH CLEARANCE FROM ALL COPPER FEATURES, | THE STARTING COPPER WEIGHT/THICKNESS CAN VARY AS LONG AS THE FINISHED COPPER | WEIGHT/THICKNESS IS NOT LESS THAN THE SPECIFIED VALUE. | UNLESS OTHERWISE SPECIFIED | WORKMANSHIP SHALL CONFORM TO IPC-A-600, CLASS 2. | 21.  INTENTIONAL SHORTS: | 17.  FINAL ELECTRICAL TEST TO BE PERFORMED USING PROVIDED IPC-D-356A NETLIST OR ODB++ FORMAT FILE. | 22.  PEMNUTS: | 23.  MANUFACTURER TO ETCH/STAMP WITH PERMANENT NON-CONDUCTIVE INK | ON SECONDARY SIDE UNLESS OTHERWISE SPECIFIED: | 18.  A TIME DOMAIN REFLECTOMETER REPORT (TDR) FOR EACH IMPEDANCE CONTROLLED LAYER & A CERTIFICATE | 19.  IF PRESENT, ALL BLIND/BURIED VIAS WITH AN ASPECT RATIO <1:1 TO BE PLATED SHUT WITH COPPER WHEN | 20.  FOR VIA FILL INFORMATION REFER TO DRILL CHART: | 25. PANELIZATION: | 27.  MINIMUM DESIGN LINE WIDTH IS .005 INCH. | 28.  MINIMUM DESIGN LINE SPACING IS .005 INCH. | IS ACCEPTABLE, ALL OTHER INSTANCES MUST BE REPORTED. | IF AN INTENTIONAL SHORT REPORT IS SUPPLIED AND DOES NOT MATCH THE FAB DATA THEN | THE PCB SHALL HAVE A VERIFICATION STAMP. | (X)  NON-CONDUCTIVE EPOXY FILL ALL 0.008-INCH AND 0.010-INCH DRILLED VIAS | ( )  COPPER FILL ALL 0.XXXX INCHES DRILLED VIAS | ( ) PEMNUTS TO BE INSTALLED BY FABRICATOR | ( ) PEMNUTS NOT TO BE INSTALLED BY FABRICATOR | (X) NOT APPLICABLE | USED AS VIA-IN-PAD OR AS A STACKED VIA. BLIND/BURIED VIAS WITH AN ASPECT RATIO >1:1 TO BE FILLED | A. UL CODE-FLAMMABILITY RATING FOR THOSE APPROVED MATERIALS(IF APPLICABLE) | B. DATE CODE | C. LOT NUMBER | D. MANUFACTURER LOGO | BOARDS TO BE SHIPPED IN ARRAY AND KEPT INTACT | PANEL TO BE SUBJECTED TO CUSTOMERS APPROVAL | PANEL SOLDER PASTE STENCIL GERBER TO BE PROVIDED TO ANALOG | CAN'T BE PERFORMED BECAUSE THE TRACE LENGTH IS TOO SHORT ON THE OUTER LAYERS AT THE PIN ESCAPES | ADI APPROVAL IS REQUIRED. | OF COMPLIANCE SHALL BE PROVIDED BY VENDOR AT TIME OF SHIPMENT. INSTANCES WHERE TDR TESTING | WITH NON-CONDUCTIVE EPOXY. | TOOLING: | FINISH: | NOTES: | MATERIAL: | TESTING: | MISCELLANEOUS: | 4-LAYER STACKUP | B | AS PER ECR-112411 | 10JAN23 | J. LOQUINARIO | CUSTOMER EVALUATION Z
DIMENSION: - | " " | (REF) | +2/-0 MILS | DIA MAX | SEE NOTE 20
User.11: 3 | 1 | 2 | MATE ENTRY
User.17: L2 GND | 08-      -07
User.18: L3 PWR | 08-      -08
User.45: FIGURE | SIZE | 8.0 | 10.0 | 30.0 | 40.0 | 45.0 | 46.0 | 67.0 | 100.0 | 50.0 | 125.0 | PLATED | NON-PLATED | DRILL CHART: TOP to BOTTOM | ALL UNITS ARE IN MILS | QTY | 48 | 430 | 20 | 23 | 12 | 8 | 32 | 2 | 4 | TOLERANCE/NOTES | .219
